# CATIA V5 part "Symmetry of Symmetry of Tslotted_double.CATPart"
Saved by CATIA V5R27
Part number: Symmetry of Symmetry of Tslotted_double
Bounding box of the stored display mesh (mm): x -19.05 to 19.05, y -19.05 to 19.05, z -381 to 381
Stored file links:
  \\triton.meca.polymtl.ca\usagers\zaoue\profiles\Desktop\varm_ass\structure prismatique\Symmetry of Symmetry of Tslotted_double.CATPart
  \\triton.meca.polymtl.ca\usagers\zaoue\profiles\Desktop\varm_ass\structure prismatique\Symmetry of Tslotted_double.CATPart
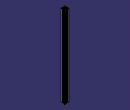
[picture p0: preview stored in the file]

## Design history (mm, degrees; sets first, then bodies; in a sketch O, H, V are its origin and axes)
Body1 (main body)
  Body2 "Corps du corps principal d'origine"
    Solid1: linked copy from another document
  Assemble1: tool Body2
